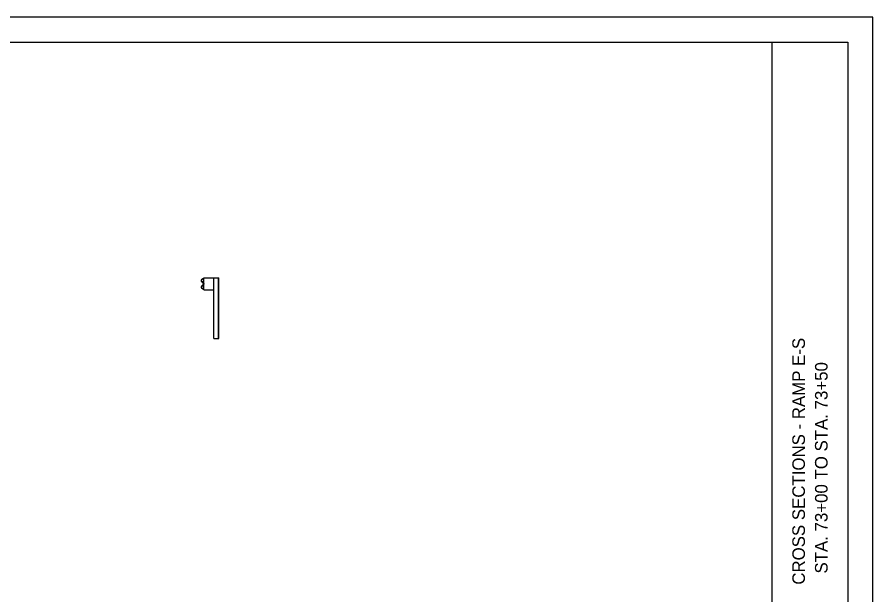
# Model space of a CAD drawing. Extents: x -31.8 to 34, y 0 to 22.
# Drawn here: x 17 to 34, y 10.52 to 22 of the extents above; entities that cross this region are included whole.
import ezdxf

# ---------------------------------------------------------------- set-up
doc = ezdxf.new("R2010")
doc.units = 0
for name, color, linetype in [('MD_P_Surface_Asphalt_Concrete_Intermediate_Course', 7, 'Continuous'), ('SH_Border', 7, 'Continuous'), ('SH_Cut_Line', 7, 'Continuous'), ('SH_Data', 7, 'Continuous')]:
    doc.layers.add(name, color=color, linetype=linetype)

msp = doc.modelspace()

# ---------------------------------------------------------------- linework, layer by layer
at = {"layer": 'MD_P_Surface_Asphalt_Concrete_Intermediate_Course'}
for p, q in [((20.655, 16.765), (20.655, 16.765)), ((20.657, 16.765), (20.657, 16.765)), ((20.691, 16.8), (20.662, 16.779)), ((20.662, 16.779), (20.662, 16.779)), ((20.662, 16.75), (20.662, 16.75)), ((20.662, 16.75), (20.7, 16.723)), ((20.7, 16.679), (20.662, 16.652)), ((20.663, 16.777), (20.692, 16.798)), ((20.663, 16.777), (20.663, 16.777)), ((20.663, 16.752), (20.663, 16.752)), ((20.701, 16.725), (20.663, 16.752)), ((20.663, 16.65), (20.701, 16.678)), ((20.686, 16.797), (20.686, 16.797)), ((20.686, 16.733), (20.686, 16.733)), ((20.687, 16.795), (20.687, 16.795)), ((20.687, 16.734), (20.687, 16.734)), ((20.708, 16.803), (20.691, 16.8)), ((20.691, 16.8), (20.691, 16.8)), ((20.692, 16.798), (20.708, 16.801)), ((20.692, 16.798), (20.692, 16.798)), ((20.7, 16.723), (20.7, 16.723)), ((20.7, 16.679), (20.7, 16.679)), ((20.701, 16.725), (20.701, 16.725)), ((20.701, 16.678), (20.701, 16.678)), ((20.706, 16.71), (20.706, 16.71)), ((20.706, 16.71), (20.706, 16.692)), ((20.706, 16.695), (20.706, 16.707)), ((20.706, 16.692), (20.706, 16.692)), ((20.708, 16.803), (20.708, 16.803)), ((20.708, 16.801), (20.708, 16.803)), ((20.708, 16.801), (20.708, 16.801)), ((20.708, 16.71), (20.708, 16.71)), ((20.708, 16.692), (20.708, 16.71)), ((20.708, 16.695), (20.708, 16.707)), ((20.708, 16.692), (20.708, 16.692)), ((20.711, 16.818), (20.911, 16.818)), ((20.711, 16.584), (20.711, 16.818)), ((20.907, 16.584), (20.907, 16.818)), ((20.91, 16.584), (20.91, 16.818)), ((20.911, 16.818), (21.007, 16.818)), ((20.911, 16.584), (20.911, 16.818)), ((21.003, 15.618), (21.003, 16.818)), ((21.007, 15.618), (21.007, 16.818)), ((20.655, 16.637), (20.655, 16.637)), ((20.657, 16.637), (20.657, 16.637)), ((20.662, 16.652), (20.662, 16.652)), ((20.662, 16.623), (20.662, 16.623)), ((20.662, 16.623), (20.69, 16.602)), ((20.663, 16.65), (20.663, 16.65)), ((20.663, 16.625), (20.663, 16.625)), ((20.691, 16.604), (20.663, 16.625)), ((20.69, 16.602), (20.708, 16.599)), ((20.708, 16.601), (20.691, 16.604)), ((20.708, 16.601), (20.708, 16.601)), ((20.708, 16.599), (20.708, 16.601)), ((20.708, 16.599), (20.708, 16.599)), ((20.711, 16.584), (20.911, 16.584)), ((20.907, 15.618), (20.907, 16.584)), ((20.91, 15.618), (20.91, 16.584)), ((20.907, 15.618), (21.007, 15.618))]:
    msp.add_line(p, q, dxfattribs=at)
for points in [[(20.704, 16.707), (20.704, 16.695), (20.699, 16.695), (20.699, 16.707)], [(20.704, 16.713), (20.704, 16.689), (20.706, 16.689), (20.706, 16.713)]]:
    msp.add_lwpolyline(points, close=True, dxfattribs=at)
for centre, radius, start, end in [((20.673, 16.765), 0.0177, 126.7788, 233.682), ((20.673, 16.765), 0.0157, 126.7788, 233.682), ((20.69, 16.71), 0.0158, 359.9056, 53.682), ((20.69, 16.692), 0.0158, 306.1293, 359.9056), ((20.69, 16.71), 0.0177, 359.9056, 53.682), ((20.69, 16.692), 0.0177, 306.1293, 359.9056), ((20.672, 16.637), 0.0177, 126.1293, 233.0325), ((20.672, 16.637), 0.0157, 126.1293, 233.0325)]:
    msp.add_arc(centre, radius, start, end, dxfattribs=at)
at = {"layer": 'SH_Border'}
msp.add_line((32, 0.5), (32, 21.5), dxfattribs=at)
msp.add_lwpolyline([(1.5, 21.5), (33.5, 21.5), (33.5, 0.5), (1.5, 0.5)], close=True, dxfattribs=at)
at = {"layer": 'SH_Cut_Line'}
msp.add_lwpolyline([(0, 0), (34, 0), (34, 22), (0, 22)], close=True, dxfattribs=at)

# ---------------------------------------------------------------- texts
at = {"layer": 'SH_Data'}
for s, p in [('CROSS SECTIONS - RAMP E-S', (32.65, 10.725)), ('STA. 73+00 TO STA. 73+50', (33.1, 10.947))]:
    msp.add_text(s, height=0.25, rotation=90, dxfattribs=at).set_placement(p)

doc.saveas('drawing.dxf')
